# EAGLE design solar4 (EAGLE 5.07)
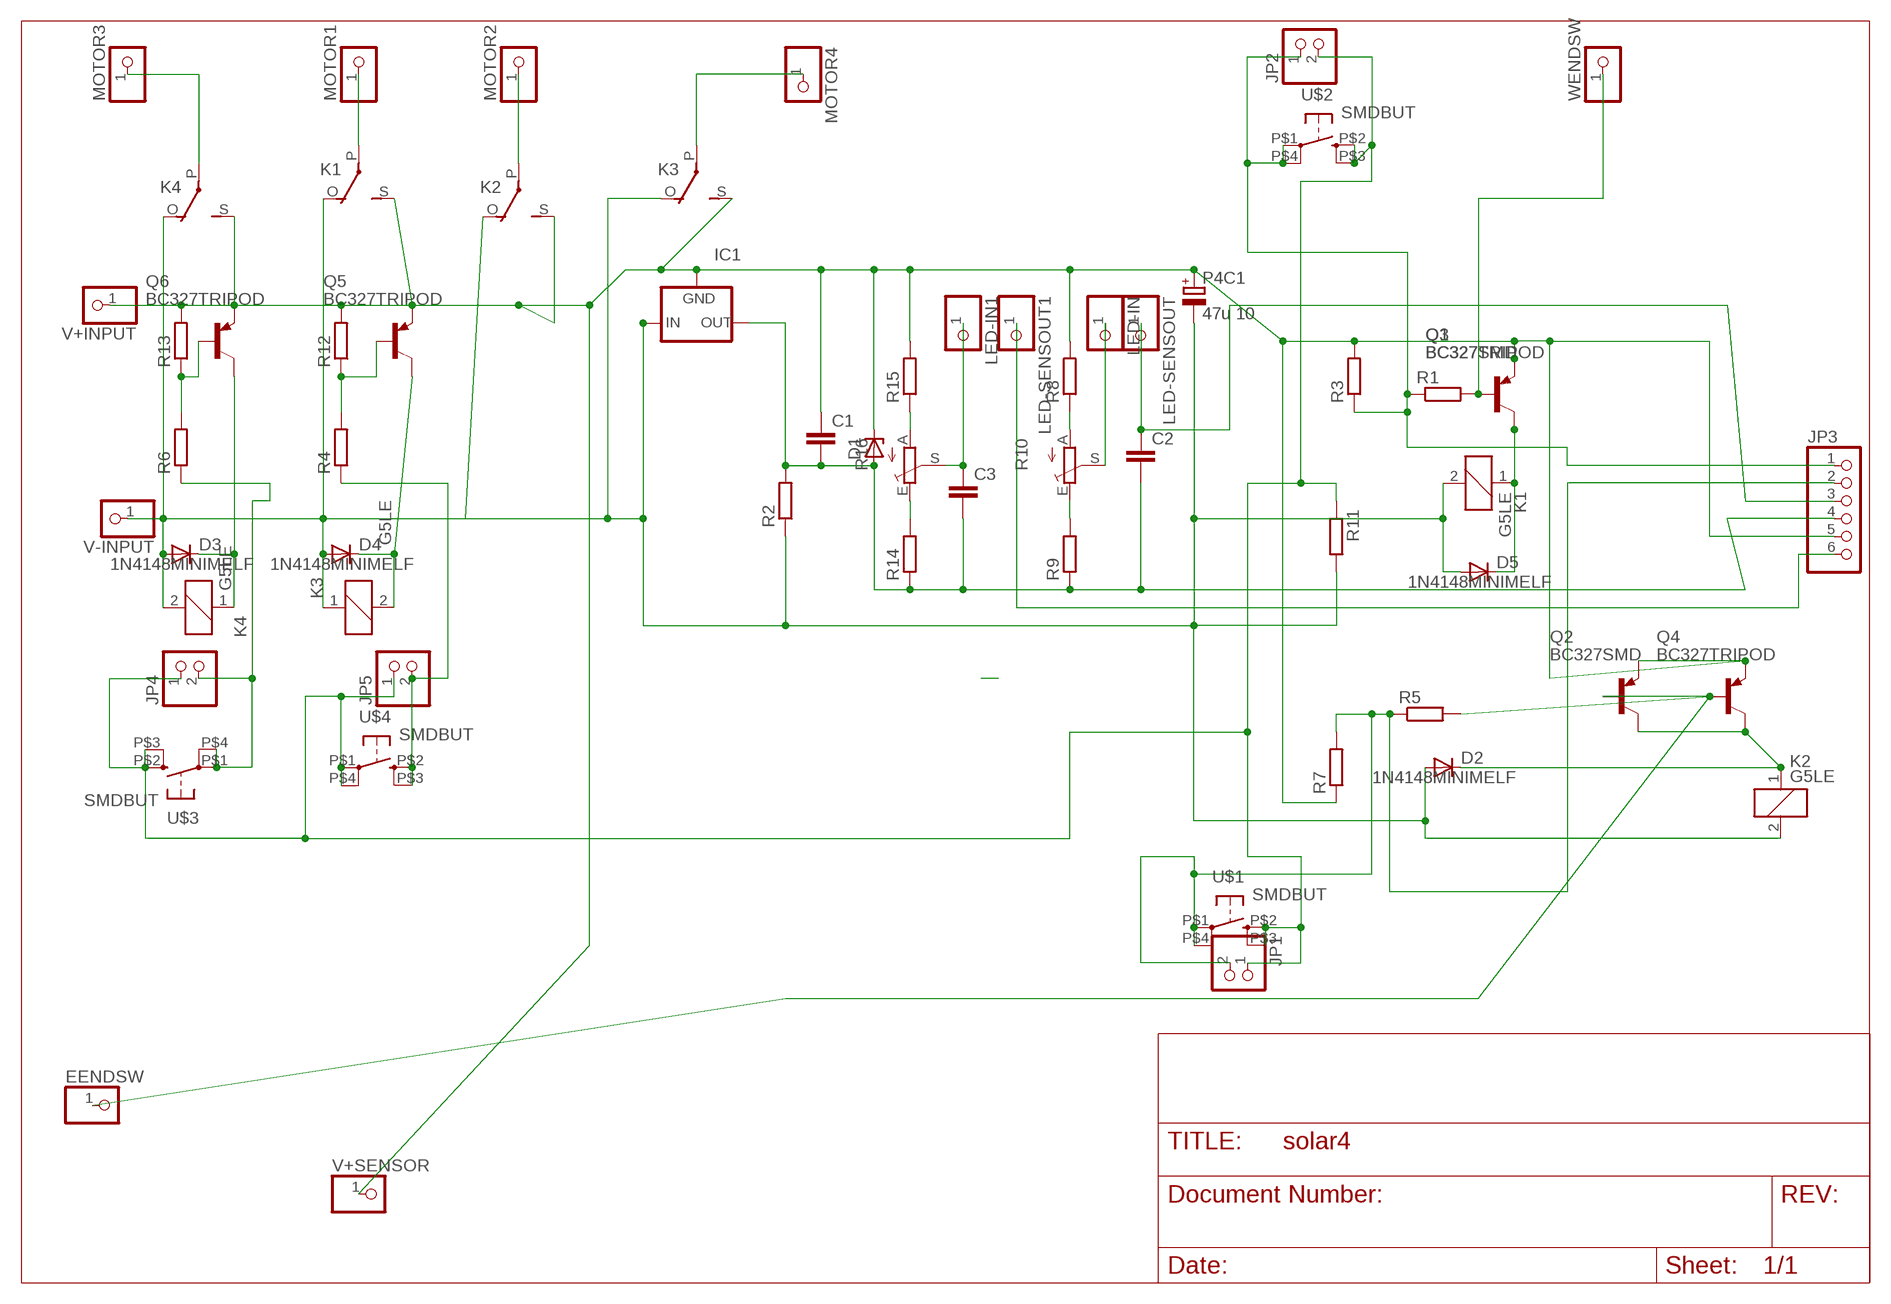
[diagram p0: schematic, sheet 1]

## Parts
C1  C-EUC1206  [C1206]
C2  C-EUC1206  [C1206]
C3  C-EUC1206  [C1206]
D1  ZENER-DIODESOD80C  [SOD80C]
D2  1N4148MINIMELF  [MINIMELF]
D3  1N4148MINIMELF  [MINIMELF]
D4  1N4148MINIMELF  [MINIMELF]
D5  1N4148MINIMELF  [MINIMELF]
EENDSW  PINHD-1X1  [1X01]
IC1  79LXX  [79LXX]
JP1  PINHD-1X2  [1X02X05]
JP2  PINHD-1X2  [1X02X05]
JP3  PINHD-1X6  [1X06BOX]
JP4  PINHD-1X2  [1X02X05]
JP5  PINHD-1X2  [1X02X05]
K1  G5LE  [G5LE]
K2  G5LE  [G5LE]
K3  G5LE  [G5LE]
K4  G5LE  [G5LE]
LED-IN  PINHD-1X1  [1X01]
LED-IN1  PINHD-1X1  [1X01]
LED-SENSOUT  PINHD-1X1  [1X01]
LED-SENSOUT1  PINHD-1X1  [1X01]
MOTOR1  PINHD-1X1  [1X01]
MOTOR2  PINHD-1X1  [1X01]
MOTOR3  PINHD-1X1  [1X01]
MOTOR4  PINHD-1X1  [1X01]
P4C1  47u 10  CPOL-EUE5-8.5  [E5-8,5]
Q1  BC327SMD  [SOT23-BEC]
Q2  BC327SMD  [SOT23-BEC]
Q3  BC327TRIPOD  BC327  [TO92]
Q4  BC327TRIPOD  BC327  [TO92]
Q5  BC327TRIPOD  BC327  [TO92]
Q6  BC327TRIPOD  BC327  [TO92]
R1  R-EU_R1206  [R1206]
R2  R-EU_R1206  [R1206]
R3  R-EU_R1206  [R1206]
R4  R-EU_R1206  [R1206]
R5  R-EU_R1206  [R1206]
R6  R-EU_R1206  [R1206]
R7  R-EU_R1206  [R1206]
R8  R-EU_R1206  [R1206]
R9  R-EU_R1206  [R1206]
R10  TRIM_EU-CA6V  [CA6V]
R11  R-EU_R1206  [R1206]
R12  R-EU_R1206  [R1206]
R13  R-EU_R1206  [R1206]
R14  R-EU_R1206  [R1206]
R15  R-EU_R1206  [R1206]
R16  TRIM_EU-CA6V  [CA6V]
U$1  SMDBUT  [SMD10/5]
U$2  SMDBUT  [SMD10/5]
U$3  SMDBUT  [SMD10/5]
U$4  SMDBUT  [SMD10/5]
V+INPUT  PINHD-1X1  [1X01]
V+SENSOR  PINHD-1X1  [1X01]
V-INPUT  PINHD-1X1  [1X01]
WENDSW  PINHD-1X1  [1X01]

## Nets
MOTO1: K2.P(2:P) MOTOR2.1
MOTO2: K1.P(2:P) MOTOR1.1
N$1: R9.2 R10.E
N$2: K4.P(2:P) MOTOR3.1
N$3: LED-IN.1 R10.S
N$4: K3.P(2:P) MOTOR4.1
N$5: C1.2 C2.2 C3.2 D1.A IC1.OUT JP3.4 R2.2 R9.1 R14.1
N$6: JP1.1 JP2.2 JP4.1 JP5.1 R11.1 U$1.P$2(S) U$1.P$3(S1) U$2.P$2(S) U$2.P$3(S1) U$3.P$2(S) U$3.P$3(S1) U$4.P$1(P) U$4.P$4(P1)
N$7: C2.1 JP3.3 LED-SENSOUT.1
N$8: Q1.B Q3.2(B) R1.2 WENDSW.1
N$9: JP4.2 R6.1 U$3.P$1(P) U$3.P$4(P1)
N$11: D5.C K1.1 Q1.C Q3.3(C)
N$12: D4.C K3.2 Q5.3(C)
N$13: JP2.1 JP3.1 R1.1 R3.1 U$2.P$1(P) U$2.P$4(P1)
N$14: JP1.2 JP3.2 R5.1 R7.2 U$1.P$1(P) U$1.P$4(P1)
N$15: EENDSW.1 Q2.B Q4.2(B) R5.2
N$16: D3.C K4.1 Q6.3(C)
N$17: JP5.2 R4.1 U$4.P$2(S) U$4.P$3(S1)
N$18: R8.1 R10.A
N$19: Q6.2(B) R6.2 R13.1
N$20: Q5.2(B) R4.2 R12.1
N$21: R14.2 R16.E
N$22: R15.1 R16.A
N$23: C3.1 LED-IN1.1 R16.S
N$24: JP3.6 LED-SENSOUT1.1
Q1-C: D2.C K2.1 Q2.C Q4.3(C)
V+: C1.1 D1.C IC1.GND JP3.5 K1.S(2:S) K2.S(2:S) K3.S(2:S) K4.S(2:S) P4C1.+ Q1.E Q2.E Q3.1(E) Q4.1(E) Q5.1(E) Q6.1(E) R3.2 R7.1 R8.2 R12.2 R13.2 R15.2 V+INPUT.1 V+SENSOR.1
V-: D2.A D3.A D4.A D5.A IC1.IN K1.2 K1.O(2:O) K2.2 K2.O(2:O) K3.1 K3.O(2:O) K4.2 K4.O(2:O) P4C1.- R2.1 R11.2 V-INPUT.1

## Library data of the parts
C1-C3 = rcl-2:C-EU: CAPACITOR, European symbol
D1 = diode-1:ZENER-DIODE: Z-Diode
D2-D5 = diode-1:1N4148: DIODE
EENDSW LED-IN LED-IN1 LED-SENSOUT LED-SENSOUT1 MOTOR1-MOTOR4 V+INPUT V+SENSOR V-INPUT WENDSW = pinhead(2):PINHD-1X1: PIN HEADER
IC1 = v-reg:79LXX: VOLTAGE REGULATOR
JP1 JP2 JP4 JP5 = pinhead:PINHD-1X2: PIN HEADER
JP3 = pinhead:PINHD-1X6: PIN HEADER
K1-K4 = relay:G5LE: RELAY 1 x switch, 10 A/120 V AC, 8 A/30 V DC, Omron
P4C1 = rcl:CPOL-EU: POLARIZED CAPACITOR, European symbol
Q1 Q2 = transistor-pnp:BC327*: PNP Transistror
Q3-Q6 = transistor-pnp:BC327: PNP Transistor
R1-R9 R11-R15 = rcl-2:R-EU_: RESISTOR, European symbol
R10 R16 = pot:TRIM_EU-: POTENTIOMETER
U$1-U$4 = switch-omron:SMDBUT

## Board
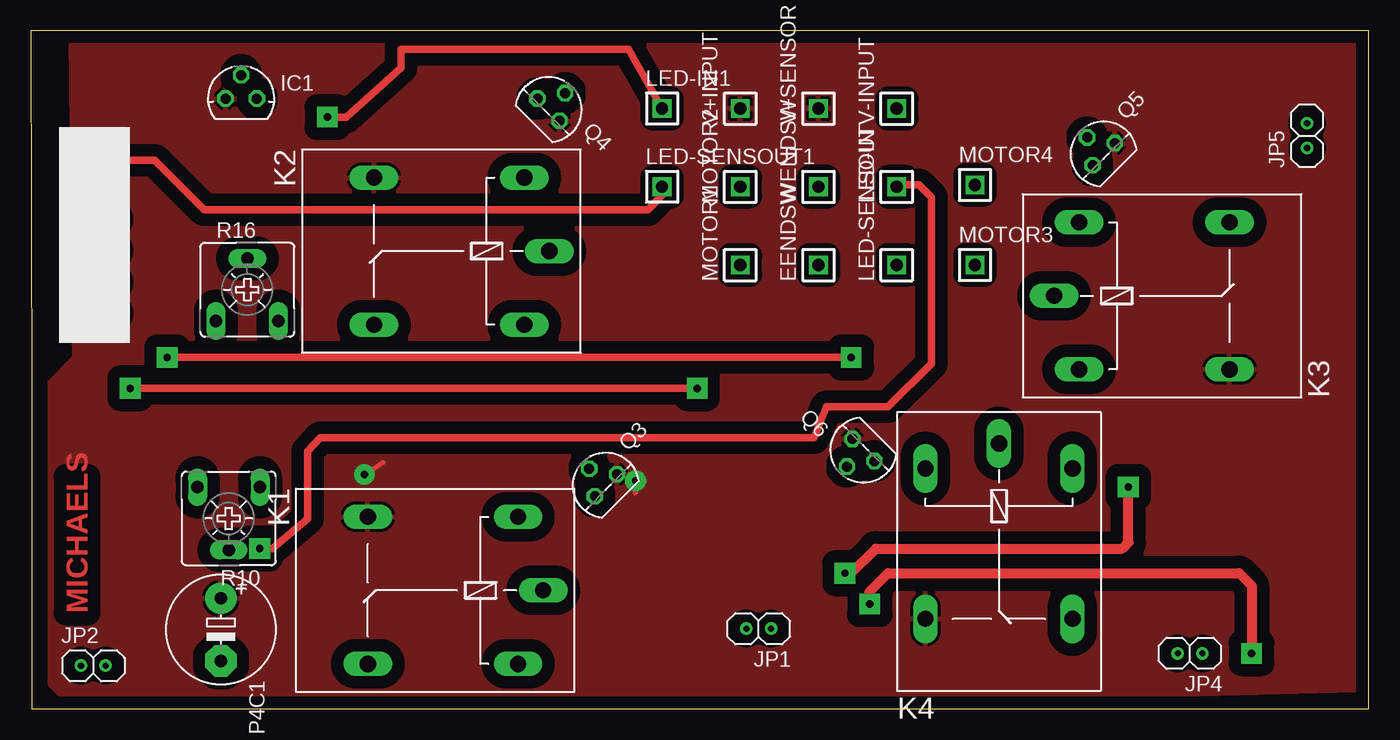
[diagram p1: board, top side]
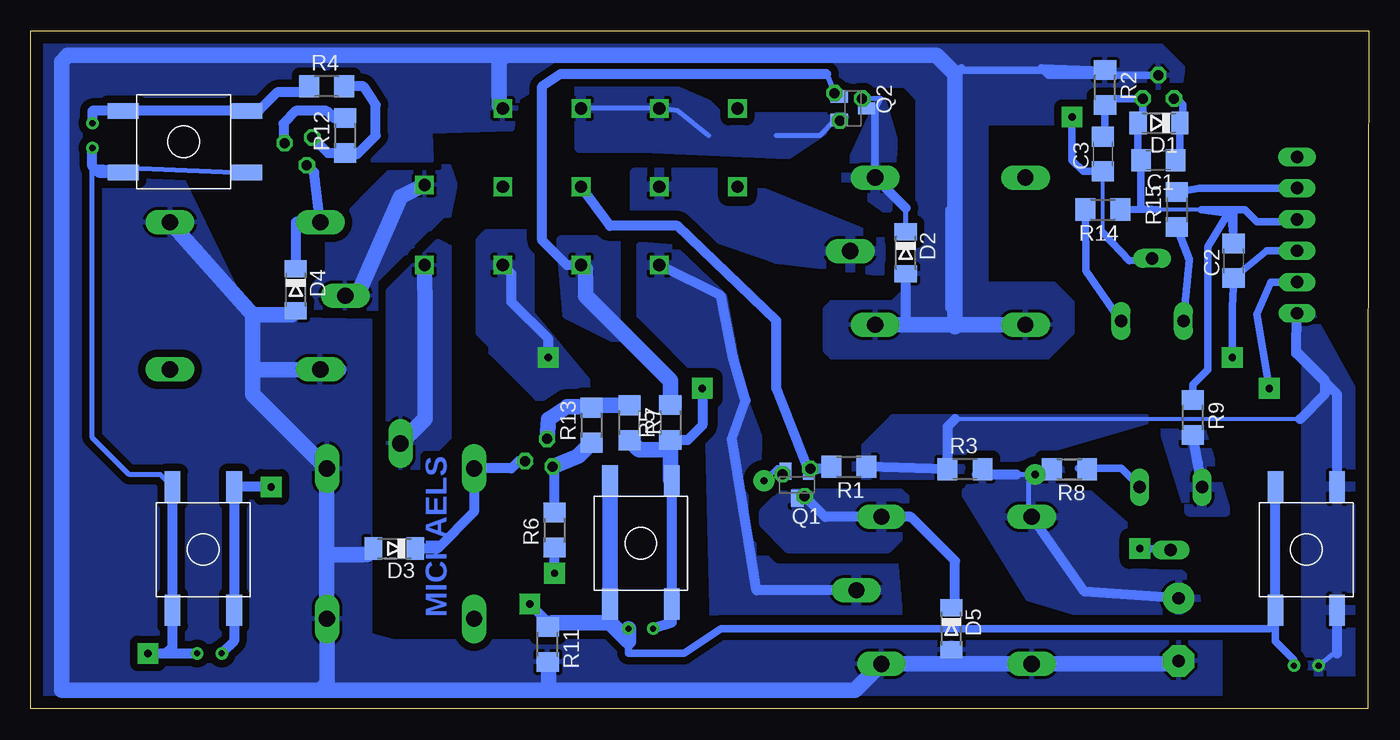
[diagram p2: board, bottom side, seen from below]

Size 108.57 x 55 mm. Coordinates in mm from the lower left corner, seen from the top.
Outline: 0.07,0 108.57,0 108.57,55 0,55 0.07,25 0.07,0
Copper layers (1*16): Top 0.035mm / dielectric 1.5mm / Bottom 0.035mm
Design rules "default *": minimum track width 40mil, minimum drill 30mil, track to track 8mil, track to pad 8mil, pad to pad 8mil, via to via 8mil, smd to smd 8mil, copper to edge 40mil, drill to drill 8mil, minimum pad ring 10mil, minimum via ring 8mil, stop-mask expansion 4mil, vias tented up to drill 0mil, thermal gap 10mil

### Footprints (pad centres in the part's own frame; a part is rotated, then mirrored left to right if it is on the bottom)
C1206 = smd 1.6 x 1.8: 1 -1.4,0; 2 1.4,0
SOD80C = smd 1.4 x 1.8: A 1.7,0; C -1.7,0
MINIMELF = smd 1.4 x 1.8: A 1.7,0; C -1.7,0
1X01 = drill 1 pad 1.27 square: 1 0,0
79LXX = drill 0.813 octagon: GND -1.27,0; IN 0,1.905; OUT 1.27,0
1X02X05 = drill 0.5 pad 0.813 round: 1 -1,0; 2 1,0
1X06BOX = drill 1 long: 1 -6.35,0; 2 -3.81,0; 3 -1.27,0; 4 1.27,0; 5 3.81,0 | drill 1.016 long: 6 6.35,0
G5LE = drill 1.321 long: 1 -7.493,-5.969; 2 -7.493,5.969; O 4.699,5.969; P -9.525,0; S 4.699,-5.969
E5-8,5 = drill 1 pad 2.54 round: + -2.54,0 | drill 1 pad 2.54 octagon: - 2.54,0
SOT23-BEC = smd 1 x 1.4: B -0.95,-1.1; C 0,1.1; E 0.95,-1.1
TO92 = drill 0.813 octagon: 1 1.27,0; 2 0,1.905; 3 -1.27,0
R1206 = smd 1.6 x 1.803: 1 -1.422,0; 2 1.422,0
CA6V = drill 1.016 long: A -2.54,-2.54; E 2.54,-2.54; S 0,2.54
SMD10/5 = smd 1.27 x 2.54: P$1 -2.5,0; P$2 2.5,0; P$3 2.5,10; P$4 -2.5,10

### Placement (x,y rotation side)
C1  17.07,44.5 180 bottom
C2  10.96,36.35 90 bottom
C3  21.57,45 90 bottom
D1  17.02,47.52 180 bottom
D2  37.57,37 270 bottom
D3  79.07,13 180 bottom
D4  87.07,34 270 bottom
D5  33.86,6.49 270 bottom
EENDSW  63.92,36 90 top
IC1  17.07,49.5 0 top
JP1  59.07,6.5 180 top
JP2  5.07,3.5 0 top
JP3  5.82,38.43 90 top
JP4  94.07,4.5 180 top
JP5  103.57,46.5 90 top
K1  32.05,9.61 180 top
K2  32.55,37.13 180 top
K3  92.57,33.5 0 top
K4  78.57,12 270 top
LED-IN  70.27,42.35 90 top
LED-IN1  51.22,48.7 0 top
LED-SENSOUT  70.27,36 90 top
LED-SENSOUT1  51.22,42.35 0 top
MOTOR1  57.57,36 90 top
MOTOR2  57.57,42.35 90 top
MOTOR3  76.62,36 0 top
MOTOR4  76.62,42.5 0 top
P4C1  15.43,6.42 270 top
Q1  46.38,18.17 180 bottom
Q2  41.86,48.73 270 bottom
Q3  46.67,18.13 45 top
Q4  42.01,48.6 315 top
Q5  87.07,45 45 top
Q6  67.57,21 135 top
R1  42.18,19.65 180 bottom
R2  21.39,50.39 270 bottom
R3  32.76,19.44 0 bottom
R4  84.57,50.5 0 bottom
R5  56.67,23.23 90 bottom
R6  66.07,14.5 90 bottom
R7  59.98,23.21 270 bottom
R8  24.28,19.44 180 bottom
R9  14.28,23.63 270 bottom
R10  16.06,15.44 180 top
R11  66.62,5.22 270 bottom
R12  83.07,46.5 90 bottom
R13  63.07,23 90 bottom
R14  21.57,40.5 180 bottom
R15  15.57,40.5 90 bottom
R16  17.57,34 0 top
U$1  59.07,18.5 180 bottom
U$2  5.07,18 180 bottom
U$3  94.57,18 180 bottom
U$4  91.07,46 90 bottom
V+INPUT  57.57,48.7 90 top
V+SENSOR  63.92,48.7 90 top
V-INPUT  70.27,48.7 90 top
WENDSW  63.92,42.35 90 top

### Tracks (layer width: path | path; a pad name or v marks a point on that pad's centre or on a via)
MOTO1
  pour Bottom (isolate 0.813, rank 3): 39.57,38 53.07,43.5 59.57,43.5 59.57,40.5 48.07,36.5 39.57,35.5
MOTO2
  Bottom 0.813: K1.P 49.68,9.61 51.68,21.89 50.57,25 51.57,28.5 52.57,33.5 MOTOR1.1
  pour Bottom (isolate 0.813, rank 4): 38.57,12 50.07,12 49.57,22 51.07,26 53.07,37 59.07,37.5 59.07,32 53.57,26.5 53.07,6.5 38.07,6.5
N$1
  Bottom 0.813: R10.E 13.85,19.93 R9.2
  pour Bottom (isolate 0.61, rank 2): 13.57,22.5 16.57,22.5 14.57,16 11.57,16
N$2
  Bottom 1.27: K4.P 76.57,23.52 76.57,33 76.62,34.95 MOTOR3.1
  pour Bottom (isolate 0.406): 74.57,37.5 74.57,22 77.07,19.5 79.07,19.5 79.57,20 79.57,34 75.57,38
N$3  (via drill 0.6 pad 1.68)
  Top 0.61: v18.57,13 19.57,13 22.47,15.4 22.47,20.9 23.47,22 63.57,22 64.57,24.5 69.57,24.5 73.07,28 73.07,41.5 72.07,42.5 70.42,42.5 LED-IN.1
  Bottom 0.406: 16.57,13 16.16,13 R10.S
  Bottom 0.61: 16.57,13 v18.57,13
N$4
  Bottom 1.27: MOTOR4.1 78.57,41.55 82.07,33.5 82.57,33.5 K3.P
  pour Bottom (isolate 0.61, rank 3): 74.57,44 79.07,44 84.57,38.5 84.57,35.5 85.57,34.5 85.57,32.5 85.07,32 80.57,32 80.07,32.5 80.07,35 75.07,40 74.57,40 74.07,42.5
N$5
  Bottom 0.305: 13.57,40.5 17.07,40.5
  Bottom 0.61: 18.47,40.52 C1.2 18.72,44.75 D1.A 18.34,47.9 IC1.OUT 20.86,49.5 R2.2 21.39,46.58 C3.2 | 18.47,40.52 R14.1 | 18.47,40.52 17.59,40.52 17.07,40.5 | R9.1 14.28,26.29 13.07,27.5 13.07,37.5 11.22,40.5 | 11.22,40.5 C2.2 10.96,40.1 13.57,40.5 11.22,40.5 | 11.22,40.5 10.07,40.5 9.07,39.5 6.02,39.5 JP3.4
N$6  (via drill 0.6 pad 1.68)
  Top 0.813: v99.07,4.5 99.07,10 98.07,11 69.57,11 68.07,9.5 v68.07,8.5
  Bottom 0.406: U$4.P$1 103.57,44 103.57,22 100.57,19 98.07,19 U$3.P$2
  Bottom 0.61: JP2.2 6.07,4 7.57,5.5 U$2.P$3 7.57,7 8.07,6.5 52.57,6.5 55.57,4.5 60.07,4.5 60.07,5.5
  Bottom 0.813: U$4.P$4 103.07,43.5 103.57,44 JP5.1 | 97.57,4.5 JP4.1 | v99.07,4.5 97.57,4.5 | v68.07,8.5 66.62,7.05 R11.1 | 97.57,4.5 97.07,5 U$3.P$3 U$3.P$2 | U$2.P$3 U$2.P$2
  Bottom 1.27: R11.1 66.26,7 61.57,7 | 61.57,7 60.07,5.5 JP1.1 | 61.57,7 U$1.P$3 U$1.P$2
N$7  (via drill 0.6 pad 1.68)
  Top 0.61: v11.07,28.5 66.07,28.5
  Top 0.813: 66.07,28.5 v66.57,28.5
  Bottom 0.61: v11.07,28.5 11.07,32.56 C2.1 8.25,37.16 JP3.3
  Bottom 0.813: v66.57,28.5 66.57,30 69.57,33 69.57,35.3 LED-SENSOUT.1
  pour Bottom (isolate 0.813, rank 2): 68.07,38.5 71.57,38.5 72.07,38 72.07,30.5 71.07,29.5 71.07,29 64.07,22 64.07,22.5 63.07,23.5 63.07,26 68.07,32
N$8
  Bottom 0.406: 44.57,19.5 R1.2
  Bottom 0.813: WENDSW.1 61.57,39.17 56.07,39.17 48.07,31.5 48.07,26 Q1.B | Q1.B 44.57,19.5 | Q3.2 Q1.B
N$9  (via drill 0.6 pad 1.68)
  Top 0.813: v89.07,18 89.07,13.5 88.57,13 68.57,13 66.57,11 v66.07,11
  Bottom 0.813: v89.07,18 U$3.P$1 U$3.P$4 92.07,5.5 JP4.2 | v66.07,11 R6.1
N$11
  Bottom 0.813: Q1.C Q3.3 44.11,15.58 K1.1 37.15,15.58 33.57,12 33.57,8.48 D5.C
  pour Bottom (isolate 0.61, rank 2): 37.57,16 37.57,14.5 39.07,13 47.07,13 49.07,15 49.07,16 47.57,17.5 38.07,17.5 37.57,17
N$12
  Bottom 0.813: Q5.3 85.58,43.51 K3.2 83.61,39.5 87.07,39.5 D4.C
N$13
  Bottom 0.305: 5.57,23.5 33.57,23.5
  Bottom 0.406: 2.57,4.5 2.8,4.5 JP2.1
  Bottom 0.813: R1.1 R3.1 34.18,22.89 33.57,23.5 | 2.57,4.5 U$2.P$4 | 5.9,29 5.9,28.82 2.57,25.5 U$2.P$1 | 5.9,29 JP3.1 | 5.57,23.5 3.57,25.5 3.57,26.68 5.9,29
  pour Bottom (isolate 0.61, rank 3): 5.07,32.5 0.07,23.5 0.57,3 5.07,3
  pour Bottom (isolate 0.61, rank 2): 18.07,23.5 38.57,23.5 41.57,20.5 41.57,19 33.57,19
N$14  (via drill 0.6 pad 1.68)
  Top 0.61: v8.07,26 v54.07,26
  Bottom 0.61: JP3.2 7.95,34.62 9.07,32 v8.07,26
  Bottom 0.813: JP1.2 56.57,7 U$1.P$4 U$1.P$1 | R5.1 55.27,21.8 54.07,23 v54.07,26
  Bottom 1.27: U$1.P$1 56.67,18.6 56.67,21 | R5.1 56.67,21 | R7.2 59.2,21 56.67,21
N$15
  Bottom 0.406: 44.02,51.5 Q4.2
  Bottom 0.813: Q2.B 43.08,49.67 Q4.2 | 44.02,51.5 65.57,51.5 67.07,50.5 67.07,38 65.07,36 EENDSW.1
  Bottom 1.27: R5.2 56.67,26.6 63.57,33.5 63.57,35.65 EENDSW.1
  pour Bottom (isolate 0.813, rank 3): 61.07,38 65.57,38 65.07,32 61.07,30
N$16
  Bottom 0.813: Q6.3 68.97,20.1 69.57,19.5 K4.1 72.6,15.97 75.57,13 D3.C
N$17
  Bottom 0.813: R4.1 86.49,50 88.57,50 90.07,48.5 U$4.P$2 U$4.P$3 103.57,48.5 JP5.2
N$18
  Bottom 0.61: R10.A 18.61,18.04 20.07,19.5 22.92,19.5 | 22.92,19.5 23.57,19.5 | 22.92,19.5 R8.1
N$19
  Bottom 0.813: Q6.2 66.07,19.5 R6.2
  Bottom 1.27: Q6.2 64.15,20.5 R13.1
N$20
  Bottom 0.813: R4.2 81.57,50.5 80.57,49 80.57,46.5 82.07,45 82.99,45 R12.1 84.45,45.08 Q5.2
N$21
  Bottom 0.61: R14.2 22.97,35.52 R16.E
N$22
  Bottom 0.61: R15.1 14.57,36.42 R16.A
N$23  (via drill 0.6 pad 1.68)
  Top 0.61: v24.07,48 25.57,48 30.07,52 30.07,53.5 48.52,53.5 LED-IN1.1
  Bottom 0.305: 21.57,38.6 C3.1
  Bottom 0.61: R16.S 19.41,36.34 21.57,38.6 | C3.1 23.17,43.6 24.07,44.5 v24.07,48
N$24
  Top 0.61: LED-SENSOUT1.1 51.22,41.65 50.07,40.5 14.07,40.5 10.07,44.5 6.1,44.5 JP3.6
Q1-C
  Bottom 0.406: 40.07,48.5 39.57,49.5 Q4.3 41.11,49.08 Q2.C | K2.1 40.07,43.13 | D2.C 37.57,40.63
  Bottom 0.61: 40.07,43.13 40.07,48.5
  Bottom 0.813: 37.57,40.63 K2.1
  pour Bottom (isolate 0.813): 39.57,49.5 42.57,43 39.07,40.5 38.57,46
V+  (via drill 0.6 pad 1.68)
  Top 0.406: v49.07,18.5 49.07,17.5 | v27.07,19 28.57,20
  Bottom 0.406: K1.S 27.57,15.58 27.57,19 | 27.57,19 28.57,19 | 31.81,19 R3.2 | V+SENSOR.1 V+INPUT.1 56.07,48.5 53.57,46.5 | Q1.E 48,19.57 v49.07,18.5 | R8.2 26.51,19.44 v27.07,19 27.57,19 | Q2.E 43.3,47.77 44.57,46.5 48.07,46.5
  Bottom 0.61: JP3.5 13.75,42.24 R15.2 | IC1.GND 15.57,49.5 15.07,49 15.07,47.77 D1.C 15.32,44.85 C1.1
  Bottom 0.813: 28.57,19 31.81,19 | P4C1.+ 23.07,9.5 K1.S | R12.2 83.99,47.92 84.57,48.5 87.07,48.5 88.07,47.5 88.07,46 Q5.1
  Bottom 1.27: R7.1 62.57,24.63 | 62.57,24.63 63.44,24.63 63.57,24.5 63.15,24.5 R13.2 | Q6.1 66.57,23.5 65.07,24.5 62.7,24.5 62.57,24.63
  pour Top (isolate 1.016, rank 5): 3.27,54.4 62.67,54.7 107.57,55 107.57,1.5 68.07,0.5 3.07,0.5 1.57,2 1.57,26.5 3.57,28.5
  pour Bottom (isolate 0.61): 47.07,45 42.57,48 52.57,48 53.57,49 57.07,50.5 64.07,50.5 64.07,45.5 59.07,45.5
  pour Bottom (isolate 0.813, rank 4): 14.07,10 25.57,20 34.07,19.5 27.57,9 17.57,6 13.57,6
V-
  Bottom 0.61: 33.89,40.32 34.07,40.5 34.07,32.5 33.57,32 | IC1.IN 25.98,51.41 26.57,52 26.57,51.99 R2.1 32.89,51.82 33.07,52 33.57,51.5
  Bottom 0.813: D2.A 37.57,31.66 37.07,31.16
  Bottom 1.27: 90.57,31.97 K3.O | K4.2 | K4.2 89.57,24.5 90.57,25.5 90.57,27.5 | 90.57,27.5 90.57,31.97 | K4.2 84.57,19.48 84.57,12.5 | 84.57,12.5 84.57,6.5 84.54,6.53 K4.O 84.54,2.03 85.07,1.5 | D3.A 81.27,12.5 84.57,12.5 | P4C1.- 15.67,3.64 K1.O K1.2 41.68,1.5 66.57,1.5 | 66.57,1.5 85.07,1.5 | R11.2 66.57,3.75 66.57,1.5 | V-INPUT.1 70.57,49 70.57,52.5 | 70.07,53 70.57,52.5 | 70.07,53 35.07,53 33.57,51.5 33.57,32 33.57,31 | 33.57,31 33.41,31.16 K2.O | 33.57,31 33.73,31.16 37.07,31.16 K2.2 | 70.57,52.5 70.57,53 | 85.07,1.5 106.07,1.5 106.07,52.5 105.57,53 70.07,53 | K3.1 83.61,27.5 90.57,27.5 | D4.A 87.4,31.97 90.57,31.97
  pour Bottom (isolate 0.61, rank 2): 12.07,5.5 12.07,0.5 108.07,0.5 108.57,1 108.57,54 107.57,55 17.07,54 15.07,52 15.57,49 15.57,47.5 31.07,47.5 31.07,34.5 25.57,34.5 24.07,33 24.07,30.5 26.07,28.5 43.57,28.5 44.07,29 44.07,32.5 43.57,33 38.57,33 36.57,35 36.57,49.5 37.57,50.5 66.57,51 69.07,49.5 69.57,47 76.17,46.8 76.07,44.5 97.07,44.5 90.87,31.7 81.07,31.5 81.07,6 79.07,5.5

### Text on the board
Top: MICHAELS
Bottom: MICHAELS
